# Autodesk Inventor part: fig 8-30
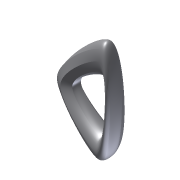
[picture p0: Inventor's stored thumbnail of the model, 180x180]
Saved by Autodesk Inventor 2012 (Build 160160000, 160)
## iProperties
Created: 2008-06
Part Number: fig 8-30
Document SubType Name: Modeling
Designer: CADCIM
Density: 1 g/cm^3
Material: Default
Author: CADCIM
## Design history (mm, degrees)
sketch "Sketch1"
  geometry: L1 (-0.077, 5.773)-(4.961, 2.953); L2 (4.961, 2.953)-(5.038, -2.82); L3 (5.038, -2.82)-(0.077, -5.773); L4 (0.077, -5.773)-(-4.961, -2.953); L5 (-4.961, -2.953)-(-5.038, 2.82); L6 (-5.038, 2.82)-(-0.077, 5.773); 1 further point
  constraints: 12 end point, 13 other
  dimensions: "d0" = 10 distance between parallel lines of L2 L5
workplane "Work Plane1"
sketch "Sketch2"
  geometry: C1 r 7.5 at (-0.159, -25); 1 further point
  constraints: 1 centre point
  dimensions: "d2" = 15 diameter of C1; "d3" = 25 vertical distance of C1.centre point (0, 0)
sketch "Sketch3" dims "d4" = 10, "d5" = 5
  geometry: 2 further points; 1 other entity
  constraints: 2 other
  dimensions: "d6" = 25 vertical distance of point (0.175, 25) point (0, 0)
loft "Loft1" sketch "Sketch2", "Sketch3" dims "d7" = 0, "d8" = 90 deg, "d9" = 0, "d10" = 90 deg, "d11" = 0, "d12" = 90 deg
body "Solid1"
other parameters: "d1" = 25
